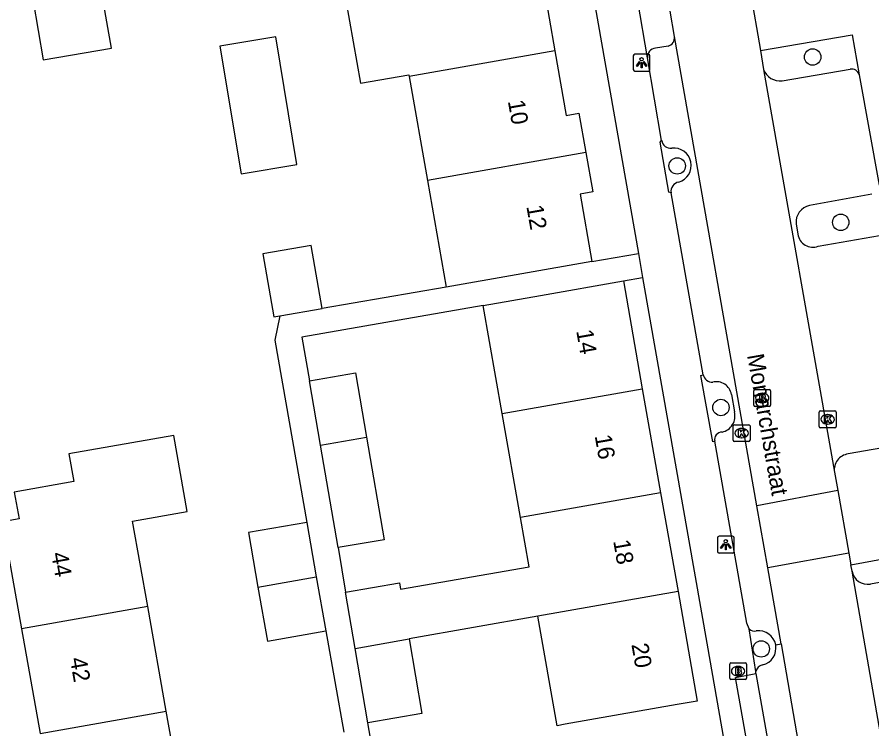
# Model space of a CAD drawing. Extents: x 162880 to 165536, y 384011 to 385179.
# Drawn here: x 164346.4 to 164397.3, y 384342.9 to 384385.3 of the extents above; entities that cross this region are included whole.
import ezdxf

# ---------------------------------------------------------------- set-up
doc = ezdxf.new("R2010")
doc.units = 0
for name, color, linetype in [('IMGEO_Boom', 7, 'Continuous'), ('IMGEO_Brandkraan', 7, 'Continuous'), ('IMGEO_Kolk', 7, 'Continuous'), ('IMGEO_Lichtpunt', 7, 'Continuous'), ('IMGEO_Openbare_ruimte_label', 7, 'Continuous'), ('IMGEO_Pand', 7, 'Continuous'), ('IMGEO_Pand_nummerreeks', 7, 'Continuous'), ('IMGEO_Parkeervlak_open', 7, 'Continuous'), ('IMGEO_Rijbaan_lokaal_open', 7, 'Continuous'), ('IMGEO_Rioolput', 7, 'Continuous'), ('IMGEO_Voetpad_open', 7, 'Continuous')]:
    doc.layers.add(name, color=color, linetype=linetype)

msp = doc.modelspace()

# ---------------------------------------------------------------- linework, layer by layer
at = {"layer": 'IMGEO_Boom'}
for centre in [(164393.744, 384382.912), (164385.683, 384376.424), (164395.418, 384373.065), (164388.286, 384362.037), (164390.686, 384347.657)]:
    msp.add_circle(centre, 0.489, dxfattribs=at)
at = {"layer": 'IMGEO_Brandkraan'}
for p, q in [((164388.808, 384345.905), (164388.808, 384346.757)), ((164388.883, 384346.831), (164389.735, 384346.831)), ((164389.809, 384346.757), (164389.809, 384345.905)), ((164389.296, 384346.611), (164389.321, 384346.611)), ((164389.735, 384345.831), (164388.883, 384345.831)), ((164389.319, 384346.051), (164389.294, 384346.051))]:
    msp.add_line(p, q, dxfattribs=at)
for points in [[(164388.808, 384345.905), (164388.808, 384346.757)], [(164388.883, 384346.831), (164389.735, 384346.831)], [(164389.809, 384346.757), (164389.809, 384345.905)], [(164389.156, 384346.531), (164389.156, 384346.131), (164389.369, 384346.131)], [(164389.387, 384346.531), (164389.156, 384346.531)], [(164389.335, 384346.45), (164389.281, 384346.45), (164389.281, 384346.374)], [(164389.281, 384346.374), (164389.334, 384346.374)], [(164389.343, 384346.298), (164389.281, 384346.298), (164389.281, 384346.217)], [(164389.281, 384346.217), (164389.343, 384346.217)], [(164389.735, 384345.831), (164388.883, 384345.831)]]:
    msp.add_lwpolyline(points, dxfattribs=at)
for centre, radius, start, end in [((164388.885, 384346.755), 0.0765, 91.552, 178.448), ((164388.885, 384346.755), 0.0765, 91.552, 178.448), ((164389.733, 384346.755), 0.0765, 1.552, 88.448), ((164389.733, 384346.755), 0.0765, 1.552, 88.448), ((164389.336, 384346.412), 0.0379, 267.8285, 90.9355), ((164389.344, 384346.257), 0.0404, 269.8759, 90.5077), ((164389.391, 384346.386), 0.145, 59.4692, 91.5367), ((164389.416, 384346.433), 0.0922, 285.5137, 58.1501), ((164389.421, 384346.241), 0.105, 301.3115, 78.989), ((164388.885, 384345.907), 0.0765, 181.552, 268.448), ((164388.885, 384345.907), 0.0765, 181.552, 268.448), ((164389.375, 384346.382), 0.251, 268.6676, 293.5347), ((164389.733, 384345.907), 0.0765, 271.552, 358.448), ((164389.733, 384345.907), 0.0765, 271.552, 358.448)]:
    msp.add_arc(centre, radius, start, end, dxfattribs=at)
for centre, major_axis, ratio, start_param, end_param in [((164389.295, 384346.331), (-0.387, 0.002), 0.722429, 4.712389, 7.853982), ((164389.32, 384346.331), (-0.39, 0.002), 0.717154, 1.570796, 4.712389)]:
    msp.add_ellipse(centre, major_axis=major_axis, ratio=ratio, start_param=start_param, end_param=end_param, dxfattribs=at)
at = {"layer": 'IMGEO_Kolk'}
for p, q in [((164394.136, 384360.905), (164394.136, 384361.757)), ((164394.211, 384361.831), (164395.063, 384361.831)), ((164394.624, 384361.611), (164394.649, 384361.611)), ((164395.137, 384361.757), (164395.137, 384360.905)), ((164389.091, 384361.01), (164389.943, 384361.01)), ((164394.647, 384361.051), (164394.622, 384361.051)), ((164389.016, 384360.084), (164389.016, 384360.936)), ((164389.504, 384360.79), (164389.529, 384360.79)), ((164390.017, 384360.936), (164390.017, 384360.084)), ((164395.063, 384360.831), (164394.211, 384360.831)), ((164389.943, 384360.01), (164389.091, 384360.01)), ((164389.527, 384360.23), (164389.502, 384360.23))]:
    msp.add_line(p, q, dxfattribs=at)
for points in [[(164394.136, 384360.905), (164394.136, 384361.757)], [(164394.211, 384361.831), (164395.063, 384361.831)], [(164394.457, 384361.531), (164394.58, 384361.531), (164394.58, 384361.38), (164394.71, 384361.531), (164394.874, 384361.531), (164394.728, 384361.38), (164394.881, 384361.131), (164394.729, 384361.131), (164394.644, 384361.295), (164394.58, 384361.228), (164394.58, 384361.131), (164394.457, 384361.131), (164394.457, 384361.531)], [(164395.137, 384361.757), (164395.137, 384360.905)], [(164389.091, 384361.01), (164389.943, 384361.01)], [(164389.016, 384360.084), (164389.016, 384360.936)], [(164389.337, 384360.71), (164389.46, 384360.71), (164389.46, 384360.559), (164389.59, 384360.71), (164389.754, 384360.71), (164389.608, 384360.559), (164389.761, 384360.31), (164389.609, 384360.31), (164389.524, 384360.474), (164389.46, 384360.407), (164389.46, 384360.31), (164389.337, 384360.31), (164389.337, 384360.71)], [(164390.017, 384360.936), (164390.017, 384360.084)], [(164395.063, 384360.831), (164394.211, 384360.831)], [(164389.943, 384360.01), (164389.091, 384360.01)]]:
    msp.add_lwpolyline(points, dxfattribs=at)
for centre, start, end in [((164394.213, 384361.755), 91.552, 178.448), ((164394.213, 384361.755), 91.552, 178.448), ((164395.061, 384361.755), 1.552, 88.448), ((164395.061, 384361.755), 1.552, 88.448), ((164389.093, 384360.934), 91.552, 178.448), ((164389.093, 384360.934), 91.552, 178.448), ((164389.941, 384360.934), 1.552, 88.448), ((164389.941, 384360.934), 1.552, 88.448), ((164394.213, 384360.907), 181.552, 268.448), ((164394.213, 384360.907), 181.552, 268.448), ((164395.061, 384360.907), 271.552, 358.448), ((164395.061, 384360.907), 271.552, 358.448), ((164389.093, 384360.086), 181.552, 268.448), ((164389.093, 384360.086), 181.552, 268.448), ((164389.941, 384360.086), 271.552, 358.448), ((164389.941, 384360.086), 271.552, 358.448)]:
    msp.add_arc(centre, 0.0765, start, end, dxfattribs=at)
for centre, major_axis, ratio, start_param, end_param in [((164394.623, 384361.331), (-0.387, 0.002), 0.722429, 4.712389, 7.853982), ((164394.648, 384361.331), (-0.39, 0.002), 0.717154, 1.570796, 4.712389), ((164389.503, 384360.51), (-0.387, 0.002), 0.722429, 4.712389, 7.853982), ((164389.528, 384360.51), (-0.39, 0.002), 0.717154, 1.570796, 4.712389)]:
    msp.add_ellipse(centre, major_axis=major_axis, ratio=ratio, start_param=start_param, end_param=end_param, dxfattribs=at)
at = {"layer": 'IMGEO_Lichtpunt'}
for p, q in [((164383.065, 384382.979), (164383.065, 384382.172)), ((164383.065, 384382.979), (164383.065, 384382.172)), ((164383.967, 384383.074), (164383.159, 384383.074)), ((164383.967, 384383.074), (164383.159, 384383.074)), ((164384.061, 384382.172), (164384.061, 384382.979)), ((164384.061, 384382.172), (164384.061, 384382.979)), ((164383.159, 384382.078), (164383.967, 384382.078)), ((164383.159, 384382.078), (164383.967, 384382.078)), ((164388.979, 384354.366), (164388.171, 384354.366)), ((164388.979, 384354.366), (164388.171, 384354.366)), ((164388.077, 384354.271), (164388.077, 384353.464)), ((164388.077, 384354.271), (164388.077, 384353.464)), ((164389.073, 384353.464), (164389.073, 384354.271)), ((164389.073, 384353.464), (164389.073, 384354.271)), ((164388.171, 384353.37), (164388.979, 384353.37)), ((164388.171, 384353.37), (164388.979, 384353.37))]:
    msp.add_line(p, q, dxfattribs=at)
for points in [[(164383.439, 384382.643), (164383.478, 384382.615), (164383.29, 384382.353), (164383.252, 384382.38), (164383.439, 384382.643)], [(164383.541, 384382.595), (164383.588, 384382.595), (164383.588, 384382.273), (164383.541, 384382.273), (164383.541, 384382.595)], [(164383.651, 384382.615), (164383.689, 384382.642), (164383.876, 384382.38), (164383.837, 384382.352), (164383.651, 384382.615)], [(164388.451, 384353.935), (164388.49, 384353.907), (164388.302, 384353.645), (164388.264, 384353.672), (164388.451, 384353.935)], [(164388.553, 384353.887), (164388.6, 384353.887), (164388.6, 384353.565), (164388.553, 384353.565), (164388.553, 384353.887)], [(164388.663, 384353.907), (164388.701, 384353.934), (164388.888, 384353.672), (164388.849, 384353.644), (164388.663, 384353.907)]]:
    msp.add_lwpolyline(points, dxfattribs=at)
for centre in [(164383.564, 384382.777), (164388.576, 384354.069)]:
    msp.add_circle(centre, 0.0994, dxfattribs=at)
for centre, start, end in [((164383.159, 384382.979), 90, 180), ((164383.159, 384382.979), 90, 180), ((164383.967, 384382.979), 0, 90), ((164383.967, 384382.979), 0, 90), ((164383.159, 384382.172), 180, 270), ((164383.159, 384382.172), 180, 270), ((164383.967, 384382.172), 270, 0), ((164383.967, 384382.172), 270, 360), ((164388.171, 384354.271), 90, 180), ((164388.171, 384354.271), 90, 180), ((164388.979, 384354.271), 0, 90), ((164388.979, 384354.271), 0, 90), ((164388.171, 384353.464), 180, 270), ((164388.171, 384353.464), 180, 270), ((164388.979, 384353.464), 270, 0), ((164388.979, 384353.464), 270, 360)]:
    msp.add_arc(centre, 0.0946, start, end, dxfattribs=at)
at = {"layer": 'IMGEO_Pand'}
for points in [[(164378.052, 384389.678), (164378.467, 384387.321), (164377.716, 384387.188), (164378.404, 384383.275)], [(164368.619, 384388.031), (164365.747, 384387.53), (164366.825, 384381.359), (164369.704, 384381.861), (164369.724, 384381.748)], [(164347.343, 384386.235), (164347.949, 384382.745), (164352.004, 384383.449), (164351.398, 384386.939), (164347.343, 384386.235)], [(164359.719, 384375.955), (164363.045, 384376.503), (164361.791, 384384.108), (164358.465, 384383.56), (164359.719, 384375.955)], [(164378.404, 384383.275), (164369.724, 384381.748)], [(164378.404, 384383.275), (164379.081, 384379.428), (164379.832, 384379.559), (164380.243, 384377.219)], [(164369.724, 384381.748), (164370.812, 384375.56)], [(164380.243, 384377.219), (164370.812, 384375.56)], [(164380.243, 384377.219), (164380.655, 384374.878), (164379.904, 384374.746), (164380.611, 384370.727)], [(164370.812, 384375.56), (164371.93, 384369.2)], [(164364.548, 384367.933), (164363.9, 384371.678), (164361.022, 384371.18), (164361.67, 384367.435), (164362.031, 384367.497)], [(164380.611, 384370.727), (164371.93, 384369.2)], [(164374.127, 384368.119), (164377.553, 384368.708), (164382.477, 384369.574)], [(164382.477, 384369.574), (164383.606, 384363.152)], [(164375.258, 384361.685), (164374.127, 384368.119)], [(164362.031, 384367.497), (164364.548, 384367.933)], [(164363.793, 384363.623), (164366.539, 384364.093), (164367.194, 384360.268)], [(164364.45, 384359.786), (164363.793, 384363.623)], [(164375.258, 384361.685), (164383.606, 384363.152)], [(164383.606, 384363.152), (164384.696, 384356.951)], [(164376.348, 384355.484), (164375.258, 384361.685)], [(164354.168, 384350.182), (164353.267, 384355.268), (164356.515, 384355.844), (164355.712, 384360.373), (164349.479, 384359.268), (164349.771, 384357.624), (164346.226, 384356.996), (164346.509, 384355.401), (164345.524, 384355.226), (164346.654, 384348.851)], [(164364.45, 384359.786), (164367.194, 384360.268)], [(164367.194, 384360.268), (164368.239, 384354.159), (164365.493, 384353.689)], [(164365.493, 384353.689), (164364.45, 384359.786)], [(164384.696, 384356.951), (164376.348, 384355.484)], [(164384.696, 384356.951), (164385.731, 384351.068)], [(164365.945, 384351.043), (164369.151, 384351.592), (164369.216, 384351.209), (164376.863, 384352.554), (164376.348, 384355.484)], [(164363.634, 384355.191), (164360.161, 384354.581), (164360.73, 384351.344)], [(164363.634, 384355.191), (164364.202, 384351.959)], [(164360.73, 384351.344), (164364.202, 384351.959)], [(164364.202, 384351.959), (164364.769, 384348.738)], [(164360.73, 384351.344), (164361.296, 384348.128), (164364.769, 384348.738)], [(164366.519, 384347.69), (164365.945, 384351.043)], [(164385.731, 384351.068), (164377.383, 384349.6)], [(164385.731, 384351.068), (164386.877, 384344.549), (164385.686, 384344.34), (164381.953, 384343.683), (164379.024, 384343.168), (164378.529, 384343.081), (164377.383, 384349.6)], [(164354.168, 384350.182), (164346.654, 384348.851)], [(164355.272, 384343.949), (164354.168, 384350.182)], [(164377.383, 384349.6), (164369.722, 384348.253)], [(164346.654, 384348.851), (164347.759, 384342.618)], [(164366.519, 384347.69), (164369.722, 384348.253)], [(164369.722, 384348.253), (164370.482, 384343.812), (164367.276, 384343.263)], [(164367.276, 384343.263), (164366.519, 384347.69)], [(164347.759, 384342.618), (164355.272, 384343.949)], [(164359.325, 384338.264), (164358.842, 384340.978), (164355.9, 384340.407), (164355.272, 384343.949)]]:
    msp.add_lwpolyline(points, dxfattribs=at)
at = {"layer": 'IMGEO_Parkeervlak_open'}
for points in [[(164391.932, 384381.493), (164395.969, 384382.185)], [(164397.272, 384374.736), (164393.567, 384374.064)], [(164392.759, 384372.975), (164392.859, 384372.351)], [(164394.072, 384371.642), (164397.728, 384372.285)], [(164388.908, 384362.814), (164389.091, 384361.776)], [(164401.191, 384352.246), (164397.181, 384351.521)]]:
    msp.add_lwpolyline(points, dxfattribs=at)
for centre, radius, start, end in [((164391.813, 384382.552), 1.066, 200.666, 276.4002), ((164396.061, 384381.713), 0.481, 16.9165, 101.034), ((164385.289, 384378.016), 0.535, 187.3981, 277.3169), ((164385.481, 384376.455), 1.037, 286.4118, 96.8603), ((164385.885, 384374.896), 0.575, 101.1085, 187.0517), ((164393.76, 384373.076), 1.006, 101.0668, 185.7849), ((164393.763, 384372.506), 0.917, 189.717, 289.6703), ((164387.76, 384364.082), 0.533, 190.9049, 274.3221), ((164388.015, 384362.671), 0.904, 9.0715, 103.7395), ((164388.151, 384361.525), 0.973, 281.9468, 14.9286), ((164388.353, 384360.129), 0.444, 90.1551, 193.6044), ((164397.024, 384352.455), 0.947, 190.5078, 279.5506), ((164390.284, 384349.168), 0.45, 224.5414, 283.9562), ((164390.529, 384347.708), 1.033, 10.4231, 97.6226)]:
    msp.add_arc(centre, radius, start, end, dxfattribs=at)
at = {"layer": 'IMGEO_Rijbaan_lokaal_open'}
for points in [[(164386.344, 384408.063), (164390.64, 384383.301)], [(164385.515, 384384.132), (164385.258, 384385.641)], [(164390.418, 384356.182), (164385.515, 384384.132)], [(164390.64, 384383.301), (164390.816, 384382.176)], [(164390.816, 384382.176), (164395.04, 384358.184)], [(164395.04, 384358.184), (164395.235, 384357.092)], [(164395.235, 384357.092), (164390.418, 384356.182)], [(164395.235, 384357.092), (164395.9, 384353.362)], [(164391.083, 384352.487), (164390.418, 384356.182)], [(164395.9, 384353.362), (164391.083, 384352.487)], [(164395.9, 384353.362), (164396.025, 384352.665)], [(164391.87, 384347.951), (164391.083, 384352.487)], [(164396.093, 384352.282), (164396.025, 384352.665)], [(164403.691, 384308.62), (164396.093, 384352.282)], [(164391.87, 384347.951), (164392.989, 384341.505)]]:
    msp.add_lwpolyline(points, dxfattribs=at)
at = {"layer": 'IMGEO_Rioolput'}
for p, q in [((164390.244, 384362.175), (164390.244, 384363.027)), ((164390.319, 384363.101), (164391.171, 384363.101)), ((164391.245, 384363.027), (164391.245, 384362.175)), ((164390.732, 384362.881), (164390.757, 384362.881)), ((164391.171, 384362.101), (164390.319, 384362.101)), ((164390.755, 384362.321), (164390.73, 384362.321))]:
    msp.add_line(p, q, dxfattribs=at)
for points in [[(164390.244, 384362.175), (164390.244, 384363.027)], [(164390.319, 384363.101), (164391.171, 384363.101)], [(164391.245, 384363.027), (164391.245, 384362.175)], [(164390.833, 384362.799), (164390.581, 384362.801), (164390.581, 384362.401)], [(164390.581, 384362.401), (164390.705, 384362.401), (164390.705, 384362.563), (164390.716, 384362.563)], [(164390.759, 384362.72), (164390.705, 384362.72), (164390.705, 384362.639)], [(164390.705, 384362.639), (164390.757, 384362.639)], [(164390.763, 384362.534), (164390.834, 384362.401), (164390.974, 384362.401), (164390.909, 384362.527)], [(164391.171, 384362.101), (164390.319, 384362.101)]]:
    msp.add_lwpolyline(points, dxfattribs=at)
for centre, radius, start, end in [((164390.321, 384363.025), 0.0765, 91.552, 178.448), ((164390.321, 384363.025), 0.0765, 91.552, 178.448), ((164391.169, 384363.025), 0.0765, 1.552, 88.448), ((164391.169, 384363.025), 0.0765, 1.552, 88.448), ((164390.715, 384362.51), 0.0533, 26.0293, 88.6989), ((164390.741, 384362.828), 0.19, 274.7715, 282.9687), ((164390.765, 384362.624), 0.0964, 77.0061, 93.1865), ((164390.779, 384362.681), 0.0378, 276.6634, 79.6772), ((164390.832, 384362.689), 0.109, 350.3612, 89.416), ((164390.83, 384362.689), 0.112, 277.5842, 350.9817), ((164390.814, 384362.474), 0.108, 29.5134, 73.7905), ((164390.321, 384362.177), 0.0765, 181.552, 268.448), ((164390.321, 384362.177), 0.0765, 181.552, 268.448), ((164391.169, 384362.177), 0.0765, 271.552, 358.448), ((164391.169, 384362.177), 0.0765, 271.552, 358.448)]:
    msp.add_arc(centre, radius, start, end, dxfattribs=at)
for centre, major_axis, ratio, start_param, end_param in [((164390.731, 384362.601), (-0.387, 0.002), 0.722429, 4.712389, 7.853982), ((164390.756, 384362.601), (-0.39, 0.002), 0.717154, 1.570796, 4.712389)]:
    msp.add_ellipse(centre, major_axis=major_axis, ratio=ratio, start_param=start_param, end_param=end_param, dxfattribs=at)
at = {"layer": 'IMGEO_Voetpad_open'}
for points in [[(164376.786, 384408.768), (164379.945, 384390.79), (164383.375, 384371.211)], [(164383.911, 384382.867), (164383.331, 384386.232)], [(164390.64, 384383.301), (164396.094, 384384.236), (164396.521, 384381.853)], [(164385.146, 384383.558), (164384.386, 384383.44)], [(164384.758, 384377.947), (164383.911, 384382.867)], [(164396.521, 384381.853), (164397.701, 384375.282)], [(164385.314, 384374.825), (164385.192, 384374.863), (164384.665, 384377.834), (164384.758, 384377.947)], [(164387.236, 384363.981), (164385.314, 384374.825)], [(164380.611, 384370.727), (164383.375, 384371.211)], [(164383.375, 384371.211), (164383.627, 384369.775)], [(164382.477, 384369.574), (164383.627, 384369.775)], [(164383.627, 384369.775), (164387.499, 384347.67), (164391.857, 384322.801), (164393.406, 384313.96), (164391.509, 384313.627)], [(164371.93, 384369.2), (164364.548, 384367.933)], [(164374.127, 384368.119), (164363.336, 384366.222), (164363.793, 384363.623)], [(164362.031, 384367.497), (164361.726, 384366.048), (164363.634, 384355.191)], [(164387.922, 384360.025), (164387.798, 384360.001), (164387.087, 384363.948), (164387.236, 384363.981)], [(164389.963, 384348.853), (164389.833, 384349.19), (164387.922, 384360.025)], [(164399.863, 384359.976), (164395.86, 384359.27)], [(164365.493, 384353.689), (164365.945, 384351.043)], [(164396.025, 384352.665), (164401.385, 384353.652), (164401.706, 384352.033)], [(164390.366, 384346.32), (164389.963, 384348.853)], [(164364.769, 384348.738), (164365.848, 384342.702)], [(164391.545, 384347.895), (164391.87, 384347.951)], [(164390.358, 384346.192), (164390.366, 384346.32)], [(164391.226, 384341.361), (164390.013, 384341.133), (164389.16, 384345.961), (164390.358, 384346.192)], [(164390.358, 384346.192), (164391.226, 384341.361)], [(164368.668, 384335.128), (164367.276, 384343.263)]]:
    msp.add_lwpolyline(points, dxfattribs=at)
for centre, radius, start, end in [((164384.983, 384384.068), 0.536, 287.6895, 6.8401), ((164384.431, 384382.919), 0.523, 94.9866, 185.6979), ((164395.99, 384358.319), 0.96, 97.8058, 188.0839), ((164390.528, 384347.706), 1.034, 283.4154, 10.52), ((164390.835, 384346.226), 0.478, 98.0587, 168.7183)]:
    msp.add_arc(centre, radius, start, end, dxfattribs=at)

# ---------------------------------------------------------------- texts
at = {"layer": 'IMGEO_Openbare_ruimte_label'}
msp.add_text('Monarchstraat', height=1, rotation=280.0179, dxfattribs=at).set_placement((164389.839, 384365.15))
at = {"layer": 'IMGEO_Pand_nummerreeks'}
for s, rotation, p in [('10', 279.9729, (164375.599, 384380.283)), ('12', 279.9729, (164376.701, 384374.02)), ('14', 279.9721, (164379.669, 384366.602)), ('16', 279.9721, (164380.769, 384360.345)), ('18', 279.9721, (164381.869, 384354.086)), ('44', 280.0504, (164348.417, 384353.344)), ('20', 279.9721, (164382.954, 384347.92)), ('42', 280.0504, (164349.527, 384347.078))]:
    msp.add_text(s, height=1, rotation=rotation, dxfattribs=at).set_placement(p)

doc.saveas('drawing.dxf')
